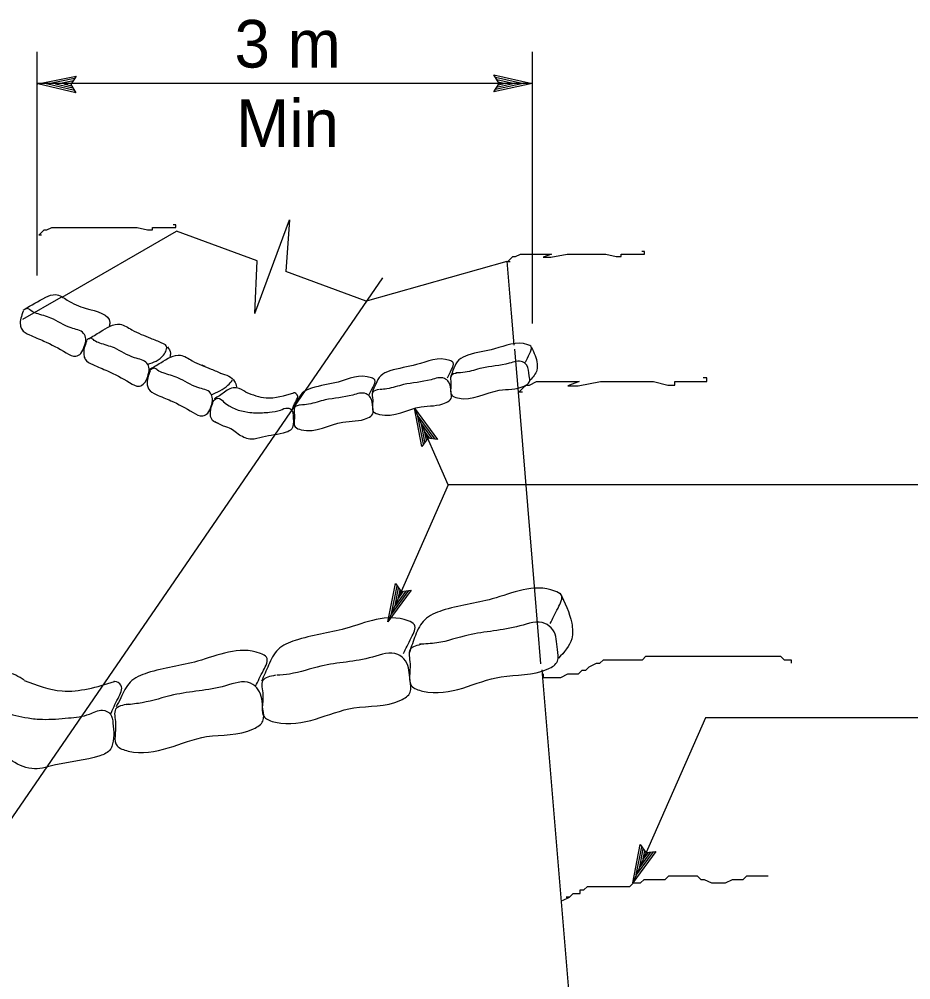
# Model space of a CAD drawing. Extents: x 6707406 to 6714471, y 1868570 to 1872341.
# Drawn here: x 6708520 to 6708654.6, y 1870275.3 to 1870420.3 of the extents above; entities that cross this region are included whole.
import ezdxf

# ---------------------------------------------------------------- set-up
doc = ezdxf.new("R2010")
doc.units = 0
for name, color, linetype in [('56 Stg 3 Anno', 7, 'Continuous'), ('57 Undefined', 7, 'Continuous'), ('60 Nongeo Data', 7, 'Continuous')]:
    doc.layers.add(name, color=color, linetype=linetype)

msp = doc.modelspace()

# ---------------------------------------------------------------- linework, layer by layer
at = {"layer": '56 Stg 3 Anno'}
for p, q in [((6708522.62, 1870415.42), (6708522.62, 1870381.62)), ((6708597.46, 1870415.42), (6708597.46, 1870374.39)), ((6708522.77, 1870410.59), (6708528.55, 1870411.75)), ((6708528.55, 1870411.75), (6708527.76, 1870410.49)), ((6708528.55, 1870411.75), (6708528.55, 1870411.75)), ((6708592.44, 1870410.62), (6708591.67, 1870411.91)), ((6708591.67, 1870411.91), (6708591.67, 1870411.91)), ((6708591.67, 1870411.91), (6708597.43, 1870410.62)), ((6708597.46, 1870410.62), (6708522.62, 1870410.62)), ((6708528.5, 1870409.19), (6708522.77, 1870410.59)), ((6708522.77, 1870410.59), (6708522.77, 1870410.59)), ((6708528.3, 1870409.54), (6708524.09, 1870410.56)), ((6708524.11, 1870410.57), (6708528.32, 1870411.41)), ((6708525.42, 1870410.54), (6708528.15, 1870411.08)), ((6708528.08, 1870409.89), (6708525.42, 1870410.54)), ((6708526.75, 1870410.51), (6708527.91, 1870410.74)), ((6708527.92, 1870410.22), (6708526.75, 1870410.51)), ((6708527.76, 1870410.49), (6708528.5, 1870409.19)), ((6708597.43, 1870410.62), (6708591.67, 1870409.34)), ((6708591.67, 1870409.34), (6708592.44, 1870410.62)), ((6708591.88, 1870411.56), (6708596.11, 1870410.62)), ((6708596.1, 1870410.62), (6708591.9, 1870409.69)), ((6708594.78, 1870410.62), (6708592.07, 1870410.02)), ((6708592.11, 1870411.22), (6708594.78, 1870410.62)), ((6708592.27, 1870410.89), (6708593.45, 1870410.62)), ((6708593.45, 1870410.62), (6708592.29, 1870410.37)), ((6708597.43, 1870410.62), (6708597.43, 1870410.62)), ((6708528.5, 1870409.19), (6708528.5, 1870409.19)), ((6708591.67, 1870409.34), (6708591.67, 1870409.34)), ((6708393.6, 1870117.38), (6708574.91, 1870381.27)), ((6708584.76, 1870350), (6708579.65, 1870361.61)), ((6708580.79, 1870355.82), (6708579.65, 1870361.61)), ((6708579.65, 1870361.61), (6708579.65, 1870361.61)), ((6708579.65, 1870361.61), (6708583.14, 1870356.86)), ((6708581.02, 1870356.15), (6708580.18, 1870360.4)), ((6708580.19, 1870360.39), (6708582.73, 1870356.92)), ((6708581.25, 1870356.5), (6708580.72, 1870359.18)), ((6708580.72, 1870359.18), (6708582.36, 1870356.95)), ((6708581.66, 1870357.04), (6708580.79, 1870355.82)), ((6708581.48, 1870356.78), (6708581.25, 1870357.97)), ((6708581.25, 1870357.97), (6708581.95, 1870357.01)), ((6708583.14, 1870356.86), (6708581.66, 1870357.04)), ((6708583.14, 1870356.86), (6708583.14, 1870356.86)), ((6708580.79, 1870355.82), (6708580.79, 1870355.82)), ((6708584.76, 1870350), (6708575.66, 1870329.32)), ((6708663.64, 1870350), (6708584.76, 1870350)), ((6708575.66, 1870329.32), (6708576.81, 1870335.11)), ((6708576.19, 1870330.55), (6708577.03, 1870334.77)), ((6708576.81, 1870335.11), (6708576.81, 1870335.11)), ((6708576.81, 1870335.11), (6708577.66, 1870333.89)), ((6708579.15, 1870334.08), (6708575.66, 1870329.32)), ((6708578.76, 1870334.03), (6708576.19, 1870330.54)), ((6708576.73, 1870331.75), (6708577.27, 1870334.48)), ((6708578.35, 1870333.96), (6708576.73, 1870331.75)), ((6708577.26, 1870332.97), (6708577.49, 1870334.13)), ((6708577.98, 1870333.94), (6708577.26, 1870332.97)), ((6708577.66, 1870333.89), (6708579.15, 1870334.08)), ((6708579.15, 1870334.08), (6708579.15, 1870334.08)), ((6708575.66, 1870329.32), (6708575.66, 1870329.32)), ((6708623.6, 1870314.81), (6708612.63, 1870289.9)), ((6708663.64, 1870314.81), (6708623.6, 1870314.81)), ((6708612.63, 1870289.9), (6708613.77, 1870295.68)), ((6708613.77, 1870295.68), (6708613.77, 1870295.68)), ((6708613.77, 1870295.68), (6708614.63, 1870294.47)), ((6708616.12, 1870294.65), (6708612.63, 1870289.9)), ((6708613.16, 1870291.12), (6708614, 1870295.34)), ((6708615.72, 1870294.6), (6708613.16, 1870291.11)), ((6708613.69, 1870292.33), (6708614.23, 1870295.05)), ((6708615.32, 1870294.53), (6708613.69, 1870292.33)), ((6708614.23, 1870293.54), (6708614.46, 1870294.7)), ((6708614.94, 1870294.51), (6708614.23, 1870293.54)), ((6708614.63, 1870294.47), (6708616.12, 1870294.65)), ((6708616.12, 1870294.65), (6708616.12, 1870294.65)), ((6708612.63, 1870289.9), (6708612.63, 1870289.9))]:
    msp.add_line(p, q, dxfattribs=at)
at = {"layer": '60 Nongeo Data'}
for p, q in [((6708555.57, 1870375.89), (6708560.78, 1870390.03)), ((6708560.78, 1870390.03), (6708560.22, 1870382.22)), ((6708526.45, 1870378.37), (6708543.72, 1870388.3)), ((6708555.57, 1870375.89), (6708555.88, 1870383.82)), ((6708572.29, 1870377.74), (6708593.69, 1870383.78)), ((6708594.74, 1870371.08), (6708593.69, 1870383.78)), ((6708520.5, 1870375.03), (6708526.29, 1870378.36)), ((6708594.71, 1870371.11), (6708594.31, 1870375.97)), ((6708595.31, 1870364.62), (6708594.82, 1870370.48)), ((6708547.54, 1870368.12), (6708547.98, 1870367.91)), ((6708597.85, 1870334.03), (6708595.31, 1870364.62)), ((6708598.76, 1870323), (6708597.85, 1870334.03)), ((6708603.97, 1870261.83), (6708598.97, 1870322.05))]:
    msp.add_line(p, q, dxfattribs=at)
for points in [[(6708523.33, 1870387.72), (6708522.94, 1870387.72), (6708523.33, 1870388.11), (6708523.72, 1870388.5), (6708524.11, 1870388.5), (6708524.89, 1870388.89), (6708525.67, 1870388.89), (6708526.06, 1870388.89), (6708526.84, 1870388.89), (6708527.62, 1870388.89), (6708528.01, 1870388.89), (6708528.4, 1870388.89), (6708529.18, 1870388.89), (6708529.57, 1870388.89), (6708529.96, 1870388.89), (6708531.13, 1870388.89), (6708531.91, 1870388.89), (6708532.3, 1870388.89), (6708532.69, 1870388.89), (6708533.08, 1870388.89), (6708533.47, 1870388.89), (6708533.86, 1870388.89), (6708534.25, 1870388.89), (6708534.64, 1870388.89), (6708535.03, 1870388.89), (6708535.81, 1870388.89), (6708536.59, 1870388.89), (6708537.37, 1870388.89), (6708537.77, 1870388.89), (6708539.33, 1870388.5), (6708540.11, 1870388.5), (6708540.11, 1870388.89), (6708540.89, 1870388.89), (6708541.28, 1870388.89), (6708541.67, 1870388.89), (6708542.06, 1870388.89), (6708542.45, 1870388.89), (6708542.84, 1870388.89), (6708543.23, 1870388.89), (6708543.23, 1870388.89), (6708543.62, 1870388.89), (6708543.62, 1870389.28), (6708543.23, 1870389.28)], [(6708555.88, 1870383.82), (6708543.72, 1870388.3)], [(6708594.13, 1870383.69), (6708593.74, 1870383.69), (6708594.13, 1870384.08), (6708594.52, 1870384.47), (6708594.91, 1870384.47), (6708595.69, 1870384.85), (6708596.47, 1870384.86), (6708596.86, 1870384.86), (6708597.64, 1870384.86), (6708598.42, 1870384.85), (6708598.81, 1870384.86), (6708599.2, 1870384.85), (6708599.98, 1870384.86), (6708600.37, 1870384.85), (6708599.11, 1870384.37), (6708600.28, 1870384.37), (6708602.72, 1870384.86), (6708603.11, 1870384.85), (6708603.5, 1870384.86), (6708603.89, 1870384.86), (6708604.28, 1870384.86), (6708604.67, 1870384.86), (6708605.06, 1870384.86), (6708605.45, 1870384.86), (6708605.84, 1870384.86), (6708606.62, 1870384.86), (6708607.4, 1870384.86), (6708608.18, 1870384.86), (6708608.57, 1870384.85), (6708610.13, 1870384.47), (6708610.91, 1870384.47), (6708610.91, 1870384.85), (6708611.69, 1870384.86), (6708612.08, 1870384.85), (6708612.47, 1870384.86), (6708612.86, 1870384.86), (6708613.25, 1870384.86), (6708613.64, 1870384.85), (6708614.03, 1870384.86), (6708614.03, 1870384.86), (6708614.42, 1870384.85), (6708614.42, 1870385.25), (6708614.03, 1870385.24)], [(6708572.38, 1870377.74), (6708560.22, 1870382.22)], [(6708595.98, 1870364.01), (6708595.45, 1870364.01), (6708595.98, 1870364.55), (6708596.52, 1870365.08), (6708597.05, 1870365.08), (6708598.12, 1870365.62), (6708599.19, 1870365.62), (6708599.73, 1870365.62), (6708600.8, 1870365.62), (6708601.87, 1870365.62), (6708602.41, 1870365.62), (6708602.94, 1870365.62), (6708604.01, 1870365.62), (6708604.55, 1870365.62), (6708602.81, 1870364.95), (6708604.41, 1870364.95), (6708607.76, 1870365.62), (6708608.29, 1870365.62), (6708608.83, 1870365.62), (6708609.36, 1870365.62), (6708609.9, 1870365.62), (6708610.43, 1870365.62), (6708610.97, 1870365.62), (6708611.5, 1870365.62), (6708612.04, 1870365.62), (6708613.11, 1870365.62), (6708614.18, 1870365.62), (6708615.25, 1870365.62), (6708615.79, 1870365.62), (6708617.93, 1870365.08), (6708619, 1870365.08), (6708619, 1870365.62), (6708620.07, 1870365.62), (6708620.6, 1870365.62), (6708621.14, 1870365.62), (6708621.67, 1870365.62), (6708622.21, 1870365.62), (6708622.74, 1870365.62), (6708623.28, 1870365.62), (6708623.28, 1870365.62), (6708623.82, 1870365.62), (6708623.82, 1870366.15), (6708623.28, 1870366.15)], [(6708599.11, 1870321.47), (6708599.11, 1870320.93), (6708599.64, 1870320.93), (6708600.71, 1870320.93), (6708601.78, 1870320.93), (6708602.85, 1870321.47), (6708603.39, 1870321.47), (6708603.92, 1870321.47), (6708604.46, 1870321.47), (6708605, 1870322), (6708605.53, 1870322), (6708606.07, 1870322.53), (6708607.14, 1870323.07), (6708607.67, 1870323.07), (6708608.21, 1870323.6), (6708608.74, 1870323.6), (6708609.28, 1870323.6), (6708609.81, 1870323.6), (6708610.35, 1870323.6), (6708610.88, 1870323.6), (6708611.42, 1870323.6), (6708611.95, 1870323.6), (6708612.49, 1870323.6), (6708613.02, 1870323.6), (6708613.56, 1870323.6), (6708614.09, 1870323.6), (6708614.63, 1870324.14), (6708615.17, 1870324.14), (6708616.24, 1870324.14), (6708617.31, 1870324.14), (6708617.84, 1870324.14), (6708618.91, 1870324.14), (6708620.52, 1870324.14), (6708621.59, 1870324.14), (6708622.12, 1870324.14), (6708623.19, 1870324.14), (6708623.73, 1870324.14), (6708624.26, 1870324.14), (6708624.8, 1870324.14), (6708625.33, 1870324.14), (6708625.87, 1870324.14), (6708626.41, 1870324.14), (6708626.94, 1870324.14), (6708628.55, 1870324.14), (6708629.08, 1870324.14), (6708631.22, 1870324.14), (6708631.76, 1870324.14), (6708632.83, 1870324.14), (6708633.36, 1870324.14), (6708633.9, 1870324.14), (6708634.43, 1870324.14), (6708634.97, 1870324.14), (6708635.5, 1870323.6), (6708636.04, 1870323.6), (6708636.04, 1870323.6), (6708636.58, 1870323.6), (6708636.58, 1870323.07)], [(6708602.03, 1870287.23), (6708603.1, 1870287.76), (6708602.57, 1870287.76), (6708603.1, 1870287.76), (6708603.64, 1870288.29), (6708604.17, 1870288.29), (6708604.71, 1870288.29), (6708604.71, 1870288.83), (6708605.24, 1870288.83), (6708605.78, 1870289.36), (6708606.31, 1870289.36), (6708607.38, 1870289.36), (6708608.99, 1870289.36), (6708609.52, 1870289.36), (6708610.06, 1870289.36), (6708611.13, 1870289.36), (6708611.67, 1870289.36), (6708612.2, 1870289.36), (6708612.74, 1870289.9), (6708613.27, 1870289.9), (6708613.81, 1870289.9), (6708614.34, 1870290.43), (6708615.41, 1870290.43), (6708616.48, 1870290.43), (6708617.55, 1870290.43), (6708618.09, 1870290.97), (6708619.16, 1870290.97), (6708619.69, 1870290.97), (6708620.77, 1870290.97), (6708621.84, 1870290.97), (6708622.37, 1870290.97), (6708622.91, 1870290.43), (6708623.44, 1870290.43), (6708624.51, 1870289.9), (6708625.05, 1870289.9), (6708625.58, 1870289.9), (6708626.65, 1870289.9), (6708627.72, 1870290.43), (6708628.26, 1870290.43), (6708629.33, 1870290.43), (6708629.86, 1870290.97), (6708630.4, 1870290.97), (6708630.93, 1870290.97), (6708632.01, 1870290.97), (6708632.54, 1870290.97), (6708633.08, 1870290.97), (6708633.08, 1870290.97)]]:
    msp.add_lwpolyline(points, dxfattribs=at)
for points in [[(6708520.73, 1870376.49), (6708523.97, 1870378.33), (6708525.44, 1870378.75), (6708527.22, 1870377.91), (6708530.05, 1870376.66), (6708533.64, 1870374.51), (6708533.55, 1870373.95)], [(6708520.56, 1870376.22), (6708520.14, 1870374.13), (6708520.35, 1870373.5), (6708521.5, 1870372.67), (6708523.7, 1870371.72), (6708527.06, 1870369.94), (6708528.53, 1870369.42), (6708529.26, 1870369.84), (6708529.79, 1870370.89), (6708530, 1870372.04), (6708529.68, 1870372.88), (6708527.79, 1870373.71), (6708524.75, 1870375.18), (6708522.55, 1870375.91), (6708521.71, 1870376.33), (6708521.19, 1870376.64), (6708520.87, 1870376.54), (6708520.56, 1870376.33)], [(6708530.46, 1870372.07), (6708532.21, 1870373.13), (6708535.19, 1870374.25), (6708536.98, 1870373.42), (6708539.81, 1870372.16), (6708541.44, 1870371.47)], [(6708530.14, 1870371.72), (6708529.72, 1870369.63), (6708529.93, 1870369), (6708531.08, 1870368.16), (6708533.29, 1870367.22), (6708536.64, 1870365.44), (6708538.11, 1870364.92), (6708538.84, 1870365.34), (6708539.37, 1870366.39), (6708539.58, 1870367.54), (6708539.26, 1870368.37), (6708537.38, 1870369.21), (6708534.33, 1870370.68), (6708532.13, 1870371.41), (6708531.29, 1870371.83), (6708530.77, 1870372.14), (6708530.45, 1870372.04), (6708530.14, 1870371.83)], [(6708539.39, 1870368.23), (6708541.76, 1870369.61), (6708542.17, 1870371.02), (6708541.41, 1870371.46)], [(6708596.43, 1870368.56), (6708597.05, 1870369.81), (6708597.31, 1870370.86), (6708596.8, 1870371.17), (6708591.77, 1870370.55), (6708587.74, 1870369.6), (6708586.36, 1870368.87), (6708585.6, 1870367.61), (6708585.14, 1870366.27)], [(6708539.58, 1870367.4), (6708541.34, 1870368.46), (6708544.32, 1870369.59), (6708546.1, 1870368.75), (6708548.94, 1870367.5), (6708550.56, 1870366.81)], [(6708542.36, 1870370.85), (6708542.8, 1870369.88), (6708542.72, 1870369.33)], [(6708597.2, 1870371.01), (6708598.15, 1870368.6), (6708598.15, 1870367.35), (6708597.1, 1870365.78)], [(6708584.64, 1870366.17), (6708585.27, 1870367.42), (6708585.52, 1870368.47), (6708585.02, 1870368.78), (6708579.98, 1870368.16), (6708575.96, 1870367.21), (6708574.57, 1870366.48), (6708573.82, 1870365.23), (6708573.26, 1870363.95)], [(6708586.18, 1870366.9), (6708585.18, 1870366.49), (6708585.18, 1870365.33), (6708585.3, 1870363.56), (6708586.18, 1870363.14), (6708592.48, 1870364.29), (6708596.25, 1870364.92), (6708597.01, 1870365.54), (6708597.01, 1870366.49), (6708596.63, 1870368.06), (6708596, 1870368.58), (6708593.99, 1870368.37), (6708589.83, 1870367.64), (6708587.32, 1870367.01), (6708585.93, 1870366.9)], [(6708539.72, 1870367.21), (6708539.3, 1870365.12), (6708539.51, 1870364.49), (6708540.66, 1870363.65), (6708542.87, 1870362.71), (6708546.22, 1870360.93), (6708547.69, 1870360.41), (6708548.43, 1870360.83), (6708548.95, 1870361.87), (6708549.16, 1870363.02), (6708548.85, 1870363.86), (6708546.96, 1870364.7), (6708543.92, 1870366.16), (6708541.71, 1870366.9), (6708540.87, 1870367.31), (6708540.35, 1870367.63), (6708540.04, 1870367.52), (6708539.72, 1870367.31)], [(6708550.31, 1870366.89), (6708552.5, 1870365.63), (6708552.77, 1870364.82)], [(6708572.78, 1870363.55), (6708573.41, 1870364.81), (6708573.66, 1870365.86), (6708573.16, 1870366.17), (6708568.12, 1870365.54), (6708564.09, 1870364.6), (6708562.71, 1870363.87), (6708561.95, 1870362.61), (6708561.58, 1870361.88)], [(6708548.95, 1870363.58), (6708551.47, 1870365.05), (6708552.17, 1870365.82)], [(6708574.36, 1870364.41), (6708573.36, 1870363.99), (6708573.36, 1870362.84), (6708573.48, 1870361.06), (6708574.36, 1870360.64), (6708580.66, 1870361.79), (6708584.43, 1870362.42), (6708585.19, 1870363.05), (6708585.19, 1870363.99), (6708584.81, 1870365.56), (6708584.18, 1870366.08), (6708582.17, 1870365.88), (6708578.01, 1870365.14), (6708575.5, 1870364.51), (6708574.47, 1870364.41)], [(6708554.21, 1870364.01), (6708552.79, 1870364.66), (6708551.76, 1870364.53), (6708550.98, 1870364.01), (6708549.43, 1870362.98)], [(6708554.19, 1870363.99), (6708557.24, 1870363.16), (6708561.45, 1870363.91)], [(6708561.13, 1870361.29), (6708561.73, 1870362.56), (6708561.96, 1870363.61), (6708561.45, 1870363.91), (6708561.4, 1870363.91)], [(6708562.54, 1870362.1), (6708561.54, 1870361.68), (6708561.54, 1870360.53), (6708561.66, 1870358.75), (6708562.54, 1870358.33), (6708568.84, 1870359.48), (6708572.61, 1870360.11), (6708573.37, 1870360.74), (6708573.37, 1870361.68), (6708572.99, 1870363.25), (6708572.36, 1870363.77), (6708570.35, 1870363.57), (6708566.19, 1870362.83), (6708563.68, 1870362.2), (6708562.41, 1870362.04)], [(6708550, 1870359.31), (6708549.16, 1870359.73), (6708548.84, 1870360.57), (6708549.16, 1870362.24), (6708549.47, 1870362.87), (6708550, 1870363.08), (6708550.84, 1870362.55), (6708554.51, 1870360.98), (6708555.66, 1870360.88), (6708557.76, 1870360.98), (6708559.44, 1870361.3), (6708560.49, 1870361.61), (6708561.12, 1870361.3), (6708561.32, 1870360.57), (6708561.22, 1870358.68), (6708561.12, 1870358.47), (6708560.28, 1870357.95), (6708556.71, 1870357.22), (6708555.03, 1870356.9), (6708553.25, 1870357.53), (6708551.47, 1870358.68), (6708550.84, 1870358.89), (6708549.58, 1870359.52)], [(6708600.17, 1870329.05), (6708601.36, 1870331.41), (6708601.83, 1870333.38), (6708600.88, 1870333.97), (6708591.41, 1870332.79), (6708583.83, 1870331.02), (6708581.23, 1870329.64), (6708579.8, 1870327.28), (6708578.94, 1870324.75)], [(6708601.63, 1870333.67), (6708603.41, 1870329.13), (6708603.41, 1870326.77), (6708601.43, 1870323.82)], [(6708578, 1870324.55), (6708579.18, 1870326.92), (6708579.65, 1870328.89), (6708578.71, 1870329.48), (6708569.23, 1870328.3), (6708561.66, 1870326.52), (6708559.05, 1870325.14), (6708557.63, 1870322.78), (6708556.57, 1870320.38)], [(6708580.9, 1870325.94), (6708579, 1870325.15), (6708579, 1870322.99), (6708579.24, 1870319.64), (6708580.9, 1870318.85), (6708592.74, 1870321.02), (6708599.84, 1870322.2), (6708601.27, 1870323.38), (6708601.27, 1870325.15), (6708600.56, 1870328.11), (6708599.37, 1870329.09), (6708595.58, 1870328.7), (6708587.77, 1870327.32), (6708583.03, 1870326.14), (6708580.42, 1870325.94)], [(6708555.67, 1870319.63), (6708556.86, 1870322), (6708557.33, 1870323.97), (6708556.39, 1870324.56), (6708546.91, 1870323.38), (6708539.33, 1870321.6), (6708536.73, 1870320.22), (6708535.31, 1870317.86), (6708534.6, 1870316.48)], [(6708558.66, 1870321.25), (6708556.76, 1870320.46), (6708556.76, 1870318.29), (6708557, 1870314.94), (6708558.66, 1870314.16), (6708570.5, 1870316.32), (6708577.6, 1870317.5), (6708579.02, 1870318.69), (6708579.02, 1870320.46), (6708578.31, 1870323.41), (6708577.13, 1870324.4), (6708573.34, 1870324), (6708565.53, 1870322.63), (6708560.79, 1870321.44), (6708558.86, 1870321.25)], [(6708520.73, 1870320.5), (6708518.06, 1870321.71), (6708516.12, 1870321.47), (6708514.66, 1870320.5), (6708511.75, 1870318.56)], [(6708520.7, 1870320.46), (6708526.43, 1870318.89), (6708534.35, 1870320.31)], [(6708533.75, 1870315.37), (6708534.89, 1870317.76), (6708535.32, 1870319.74), (6708534.36, 1870320.31), (6708534.27, 1870320.31)], [(6708536.41, 1870316.9), (6708534.52, 1870316.11), (6708534.52, 1870313.95), (6708534.76, 1870310.6), (6708536.41, 1870309.81), (6708548.26, 1870311.98), (6708555.36, 1870313.16), (6708556.78, 1870314.34), (6708556.78, 1870316.11), (6708556.07, 1870319.07), (6708554.89, 1870320.05), (6708551.1, 1870319.66), (6708543.28, 1870318.28), (6708538.55, 1870317.1), (6708536.16, 1870316.8)], [(6708512.81, 1870311.65), (6708511.23, 1870312.44), (6708510.64, 1870314.01), (6708511.23, 1870317.17), (6708511.82, 1870318.35), (6708512.81, 1870318.74), (6708514.39, 1870317.76), (6708521.29, 1870314.8), (6708523.47, 1870314.6), (6708527.41, 1870314.8), (6708530.57, 1870315.39), (6708532.54, 1870315.98), (6708533.73, 1870315.39), (6708534.12, 1870314.01), (6708533.93, 1870310.47), (6708533.73, 1870310.07), (6708532.15, 1870309.09), (6708525.44, 1870307.71), (6708522.28, 1870307.12), (6708518.93, 1870308.3), (6708515.57, 1870310.47), (6708514.39, 1870310.86), (6708512.02, 1870312.04)]]:
    msp.add_spline(points, degree=3, dxfattribs=at)

# ---------------------------------------------------------------- texts
at = {"layer": '57 Undefined'}
for s, p in [('3 m', (6708552.48, 1870413.02)), ('Min', (6708552.74, 1870401.02))]:
    msp.add_text(s, height=7.2, dxfattribs=at).set_placement(p)

doc.saveas('drawing.dxf')
